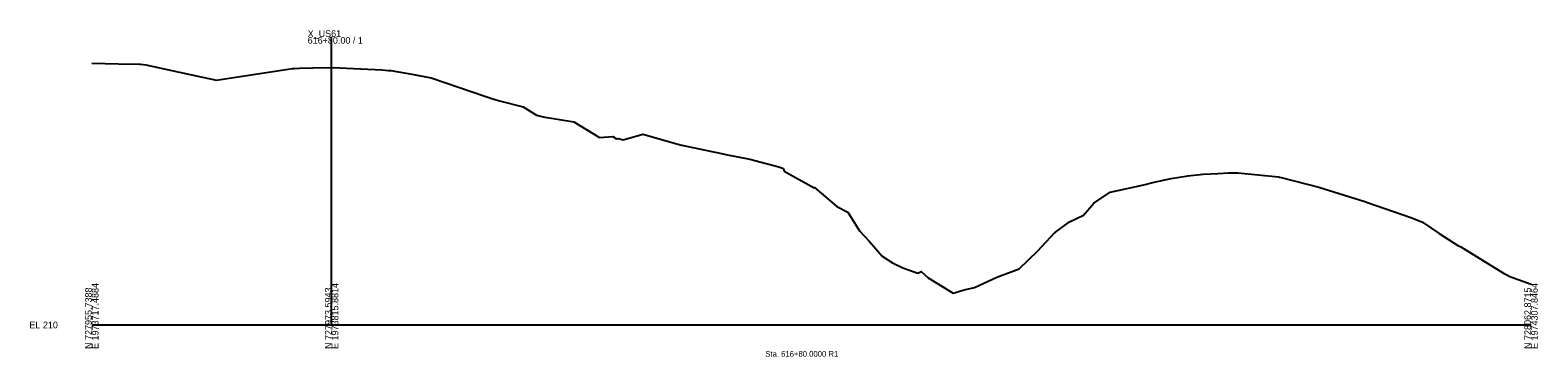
# Model space of a CAD drawing. Extents: x -26 to 1604, y -13 to 9623.
# Drawn here: x 974 to 1603, y 1987 to 2123 of the extents above; entities that cross this region are included whole.
import ezdxf

# ---------------------------------------------------------------- set-up
doc = ezdxf.new("R2010")
doc.units = 0
for name, color, linetype in [('Draft_XS_Grid', 7, 'Continuous'), ('Draft_XS_Text', 7, 'Continuous'), ('DTM_X_GROUND', 7, 'Continuous'), ('XS_CELL', 7, 'Continuous')]:
    doc.layers.add(name, color=color, linetype=linetype)

msp = doc.modelspace()

# ---------------------------------------------------------------- linework, layer by layer
at = {"layer": 'DTM_X_GROUND'}
msp.add_lwpolyline([(1000, 2109.12), (1011.08, 2108.86), (1020.06, 2108.65), (1020.47, 2108.62), (1022.57, 2108.46), (1044.25, 2103.71), (1050.71, 2102.24), (1051.92, 2102.02), (1081.88, 2106.55), (1083.65, 2106.82), (1084.47, 2106.86), (1086.6, 2106.98), (1092.13, 2107.09), (1100.61, 2107.26), (1106.16, 2107.01), (1121.1, 2106.34), (1123.58, 2106.09), (1124.71, 2105.98), (1133.38, 2104.46), (1141.46, 2103.03), (1164.26, 2095.21), (1167.23, 2094.19), (1169.93, 2093.42), (1179.9, 2090.85), (1185.41, 2087.45), (1188.15, 2086.69), (1200.92, 2084.62), (1211.62, 2078.05), (1217.22, 2078.57), (1218.76, 2077.59), (1219.58, 2077.64), (1221.53, 2077.15), (1229.67, 2079.48), (1230.7, 2079.23), (1245.8, 2074.93), (1245.92, 2074.9), (1258.53, 2072.34), (1261.28, 2071.74), (1264.31, 2071.08), (1274.33, 2069.04), (1286.39, 2065.84), (1288.3, 2065.25), (1288.6, 2064.05), (1301.19, 2057.18), (1301.25, 2057.23), (1301.29, 2057.21), (1310.63, 2049.4), (1315.2, 2047.03), (1320.11, 2039.26), (1324.17, 2034.84), (1329.53, 2028.69), (1333.86, 2025.94), (1338.14, 2023.78), (1344.34, 2021.62), (1345.79, 2022.22), (1348.72, 2019.61), (1359.11, 2013.18), (1360.05, 2013.5), (1363.7, 2014.6), (1367.98, 2015.63), (1377.3, 2019.87), (1386.66, 2023.35), (1394.41, 2030.85), (1401.46, 2038.59), (1401.72, 2038.72), (1407.6, 2043.04), (1413.41, 2045.8), (1417.76, 2050.82), (1424.58, 2055.3), (1438.52, 2058.44), (1442.91, 2059.45), (1449.93, 2061.07), (1456.87, 2062.11), (1463.36, 2062.79), (1469.52, 2063.18), (1473.87, 2063.45), (1477.8, 2063.39), (1494.75, 2061.68), (1495.14, 2061.61), (1495.79, 2061.42), (1511.51, 2057.42), (1530.77, 2051.44), (1531.19, 2051.31), (1531.27, 2051.26), (1531.43, 2051.2), (1550.35, 2044.57), (1554.78, 2042.82), (1561.65, 2038.13), (1569.54, 2033.12), (1570.78, 2032.59), (1588.56, 2021.6), (1589.97, 2020.86), (1591.12, 2020.21), (1600, 2017.03)], dxfattribs=at)
at = {"layer": 'XS_CELL'}
for p, q in [((1100, 2000), (1100, 2120)), ((1000, 2000), (1100, 2000)), ((1100, 2000), (1600, 2000))]:
    msp.add_line(p, q, dxfattribs=at)

# ---------------------------------------------------------------- texts
at = {"layer": 'Draft_XS_Grid'}
msp.add_text('-', height=0.0001, dxfattribs=at).set_placement((1000, 2000))
at = {"layer": 'Draft_XS_Text'}
msp.add_text('Sta. 616+80.0000 R1', height=2.4, dxfattribs=at).set_placement((1280.77, 1986.75))
at = {"layer": 'XS_CELL'}
for s, p in [('X_US61', (1090, 2120)), ('616+80.00 / 1', (1090, 2117.2)), ('EL 210', (974, 1998.6))]:
    msp.add_text(s, height=2.8, dxfattribs=at).set_placement(p)
for s, p in [('N 727955.7388', (1000, 1990)), ('E 1973717.4884', (1002.8, 1990)), ('N 727973.5943', (1100, 1990)), ('E 1973815.8814', (1102.8, 1990)), ('N 728062.8715', (1600, 1990)), ('E 1974307.8464', (1602.8, 1990))]:
    msp.add_text(s, height=2.8, rotation=90, dxfattribs=at).set_placement(p)

doc.saveas('drawing.dxf')
